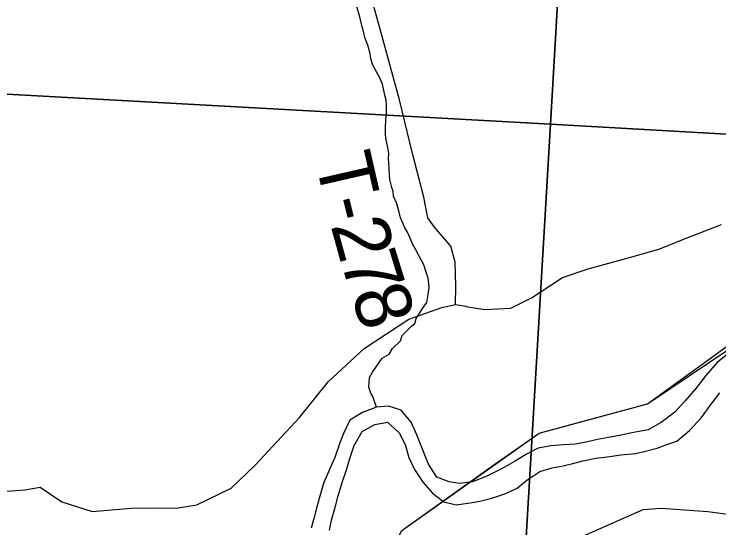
# Model space of a CAD drawing. Extents: x 0 to 34, y 0 to 22.
# Drawn here: x 4.109 to 4.825, y 16.63 to 17.152 of the extents above; entities that cross this region are included whole.
import ezdxf

# ---------------------------------------------------------------- set-up
doc = ezdxf.new("R2010")
doc.units = 0
for name, color, linetype in [('GM_P_State_Alignment', 7, 'Continuous'), ('GM_X_County_Road', 7, 'Continuous'), ('GM_X_Major_River', 7, 'Continuous'), ('GM_X_Minor_River', 7, 'Continuous'), ('GM_X_Section', 7, 'Continuous'), ('GM_X_Township_Road', 7, 'Continuous'), ('GM_X_Township_Road_Text', 7, 'Continuous'), ('SH_Data', 7, 'Continuous')]:
    doc.layers.add(name, color=color, linetype=linetype)

msp = doc.modelspace()

# ---------------------------------------------------------------- linework, layer by layer
at = {"layer": 'GM_P_State_Alignment'}
msp.add_lwpolyline([(4.40926, 16.44722), (4.46241, 16.55171), (4.50282, 16.62732), (4.55011, 16.66115), (4.59371, 16.69234), (4.64214, 16.7261), (4.67584, 16.73522), (4.75214, 16.75587), (4.84791, 16.82532), (4.91933, 16.86826), (4.9287, 16.87399), (5.03009, 16.93602), (5.04059, 16.93934), (5.06201, 16.94614), (5.20283, 16.99081), (5.21221, 16.99417), (5.27331, 17.01608), (5.30509, 17.02747), (5.3394, 17.03473), (5.52209, 17.10957), (5.54471, 17.11881), (5.5533, 17.1267), (5.65808, 17.22283)], dxfattribs=at)
at = {"layer": 'GM_X_County_Road'}
msp.add_lwpolyline([(4.51843, 16.50146), (4.52905, 16.51303), (4.5515, 16.5335), (4.58186, 16.55596), (4.60233, 16.57809), (4.63385, 16.6022), (4.67413, 16.61607), (4.6979, 16.62664), (4.74776, 16.64855), (4.76593, 16.64998), (4.78552, 16.64855), (4.81332, 16.64677), (4.83898, 16.6432)], dxfattribs=at)
at = {"layer": 'GM_X_Major_River'}
for points in [[(4.8355, 16.80809), (4.82303, 16.7978), (4.81133, 16.78486), (4.80115, 16.77155), (4.79022, 16.7586), (4.78002, 16.74756), (4.76605, 16.73689), (4.75282, 16.72964), (4.73618, 16.72656), (4.72558, 16.72425), (4.71272, 16.72193), (4.70137, 16.71962), (4.69116, 16.71732), (4.67905, 16.71501), (4.66694, 16.71421), (4.65407, 16.71342), (4.64121, 16.7111), (4.62949, 16.70499), (4.61778, 16.69775), (4.60342, 16.68973), (4.58905, 16.68248), (4.57468, 16.67674), (4.56144, 16.67519), (4.55084, 16.67668), (4.53833, 16.68158), (4.52997, 16.69484), (4.52387, 16.71002), (4.51815, 16.72443), (4.51243, 16.73733), (4.50218, 16.74945), (4.48929, 16.75359), (4.47718, 16.75242), (4.46281, 16.74706), (4.44997, 16.73943), (4.44357, 16.72574), (4.43981, 16.71624), (4.43493, 16.70142), (4.42929, 16.68925), (4.42365, 16.67594), (4.42028, 16.66454), (4.41653, 16.65124), (4.41354, 16.63945), (4.41092, 16.62957)], [(4.42947, 16.62773), (4.43133, 16.63799), (4.43546, 16.65205), (4.43808, 16.66269), (4.4422, 16.67599), (4.44671, 16.68892), (4.45008, 16.70032), (4.45458, 16.71362), (4.46249, 16.7277), (4.47534, 16.73495), (4.4882, 16.73726), (4.49997, 16.72666), (4.50606, 16.71452), (4.50989, 16.70162), (4.5156, 16.68911), (4.52434, 16.67622), (4.53384, 16.66524), (4.5456, 16.65653), (4.5581, 16.65353), (4.5721, 16.65547), (4.58193, 16.65702), (4.59404, 16.66009), (4.60728, 16.66468), (4.61975, 16.67041), (4.62957, 16.67841), (4.64279, 16.68719), (4.65527, 16.69102), (4.66662, 16.69295), (4.67646, 16.69525), (4.68667, 16.69794), (4.69991, 16.70064), (4.71391, 16.70257), (4.72526, 16.70412), (4.7404, 16.70568), (4.75137, 16.70837), (4.76196, 16.71106), (4.77179, 16.71451), (4.782, 16.71795), (4.79484, 16.729), (4.80692, 16.74194), (4.81672, 16.75564), (4.82577, 16.76706)]]:
    msp.add_lwpolyline(points, dxfattribs=at)
at = {"layer": 'GM_X_Minor_River'}
msp.add_lwpolyline([(4.47718, 16.75242), (4.47346, 16.76326), (4.47088, 16.76749), (4.46947, 16.77322), (4.47001, 16.78272), (4.47313, 16.78799), (4.48285, 16.80228), (4.49012, 16.80634), (4.49325, 16.81199), (4.50134, 16.81984), (4.50333, 16.82551), (4.5122, 16.83449), (4.51604, 16.83746), (4.51727, 16.84277), (4.52388, 16.85292), (4.52816, 16.85894), (4.52943, 16.8669), (4.53069, 16.8741), (4.53038, 16.87791), (4.52972, 16.88363), (4.52719, 16.89052), (4.52503, 16.89702), (4.52062, 16.90508), (4.51697, 16.91237), (4.51403, 16.91774), (4.51221, 16.92196), (4.50893, 16.92962), (4.50599, 16.93462), (4.50417, 16.93883), (4.50162, 16.94496), (4.50021, 16.95069), (4.49734, 16.96024), (4.49443, 16.96676), (4.49413, 16.9717), (4.49268, 16.97553), (4.49056, 16.98394), (4.49025, 16.98774), (4.49, 16.99573), (4.48971, 17.0003), (4.48941, 17.00525), (4.4895, 17.01019), (4.48847, 17.0163), (4.48709, 17.02392), (4.48642, 17.02926), (4.48617, 17.03649), (4.48668, 17.04409), (4.48718, 17.0513), (4.4873, 17.05814), (4.48703, 17.06423), (4.48596, 17.06805), (4.48455, 17.07416), (4.48315, 17.08065), (4.48024, 17.08754), (4.47583, 17.0956), (4.47325, 17.09983), (4.47147, 17.10633), (4.4708, 17.11128), (4.4683, 17.12007), (4.46541, 17.1281), (4.46436, 17.13268), (4.46222, 17.14032), (4.45974, 17.15025), (4.45724, 17.15904)], dxfattribs=at)
at = {"layer": 'GM_X_Section'}
for points in [[(3.62875, 18.10856), (4.71243, 18.04874), (4.65367, 17.04009), (3.56848, 17.09992)], [(4.71243, 18.04874), (5.78398, 17.98891), (5.72599, 16.97911), (4.65367, 17.04009)], [(3.56848, 17.09992), (4.65367, 17.04009), (4.59377, 16.02271), (3.50743, 16.08595)], [(4.65367, 17.04009), (5.72599, 16.97911), (5.67697, 16.13224), (5.6584, 16.12617), (5.62772, 16.11554), (5.59666, 16.1068), (5.53642, 16.08819), (5.51294, 16.07946), (5.48831, 16.06959), (5.4618, 16.05858), (5.43907, 16.05023), (5.42317, 16.04529), (5.40043, 16.03846), (5.37316, 16.03086), (5.308, 16.01262), (5.28868, 16.00617), (5.25686, 15.99478), (5.23679, 15.98757), (4.59377, 16.02271)]]:
    msp.add_lwpolyline(points, close=True, dxfattribs=at)
at = {"layer": 'GM_X_Township_Road'}
for points in [[(4.55744, 16.85685), (4.55777, 16.87547), (4.55695, 16.89979), (4.55273, 16.91612), (4.536, 16.93545), (4.52915, 16.94494), (4.52531, 16.96583), (4.51382, 17.01025), (4.50041, 17.06456), (4.48089, 17.13631), (4.45946, 17.21338)], [(4.56816, 16.85499), (4.56831, 16.85497), (4.5871, 16.85171), (4.61349, 16.85308), (4.63451, 16.86367), (4.66579, 16.88421), (4.69197, 16.89307), (4.73781, 16.90543), (4.76477, 16.91346), (4.7882, 16.92291), (4.82733, 16.93821)], [(4.09201, 16.66655), (4.12009, 16.66869), (4.13585, 16.6712), (4.15771, 16.65632), (4.18839, 16.64661), (4.22818, 16.64995), (4.25174, 16.65046), (4.27386, 16.65001), (4.29472, 16.65333), (4.32954, 16.67031), (4.35357, 16.69344), (4.39884, 16.74213), (4.42792, 16.77845), (4.46472, 16.81201), (4.51008, 16.84186), (4.54353, 16.85374), (4.55744, 16.85685), (4.56816, 16.85499)]]:
    msp.add_lwpolyline(points, dxfattribs=at)
at = {"layer": 'SH_Data'}
msp.add_lwpolyline([(4.37122, 16.33865), (4.46241, 16.55171), (4.50282, 16.62732), (4.64214, 16.7261), (4.75214, 16.75587), (4.91933, 16.86826), (5.04059, 16.93934), (5.20283, 16.99081), (5.3394, 17.03473), (5.52209, 17.10957), (5.5533, 17.1267), (5.65808, 17.22283), (5.72716, 17.32786), (5.78464, 17.41882), (6.03147, 17.59719)], dxfattribs=at)

# ---------------------------------------------------------------- texts
at = {"layer": 'GM_X_Township_Road_Text'}
for s, rotation, p in [('T', 282.90568, (4.41462, 17.00409)), ('-', 283.86807, (4.42436, 16.96165)), ('2', 285.45771, (4.43038, 16.93733)), ('7', 287.09122, (4.44021, 16.90191)), ('8', 288.01831, (4.4508, 16.8675))]:
    msp.add_text(s, height=0.05682, rotation=rotation, dxfattribs=at).set_placement(p)

doc.saveas('drawing.dxf')
